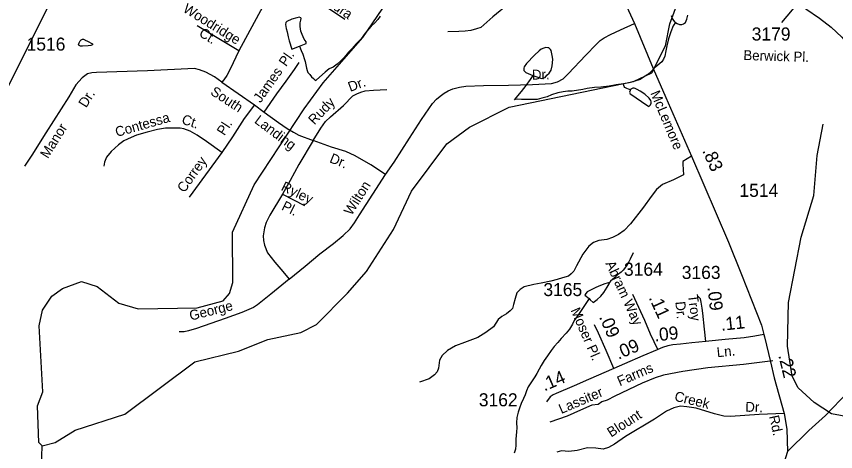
# Model space of a CAD drawing. Extents: x 2082433 to 2279600, y 546599 to 755198.
# Drawn here: x 2132963 to 2140814, y 656269 to 660438 of the extents above; entities that cross this region are included whole.
import ezdxf

# ---------------------------------------------------------------- set-up
doc = ezdxf.new("R2010")
doc.units = 0
for name, color, linetype in [('Exist Hydrographic Misc Water Feature', 7, 'Continuous'), ('Exist Road Non-System Type 51', 7, 'Continuous'), ('Exist Road Non-System Type 51 Label', 7, 'Continuous'), ('Exist Road Secondary Mileage Hundredths English Label', 7, 'Continuous'), ('Exist Road Secondary Type 51 Attributed', 7, 'Continuous'), ('Exist Road Secondary Type 51 Label', 7, 'Continuous'), ('Exist Road Secondary Type 51 Number Label', 7, 'Continuous')]:
    doc.layers.add(name, color=color, linetype=linetype)

msp = doc.modelspace()

# ---------------------------------------------------------------- linework, layer by layer
at = {"layer": 'Exist Hydrographic Misc Water Feature'}
for points in [[(2132697.5, 659397), (2133267.3, 660530.3), (2133583.5, 660799.5), (2134064.4, 661376.8), (2134486.4, 661985), (2134626.5, 662254.4), (2134800.5, 662513.3), (2134915.6, 662904.6), (2135081.5, 663114.4), (2135471.5, 663273.8), (2135853.5, 663531.7), (2136309.6, 664126.1), (2136483.7, 664253.7), (2136708.6, 664327.9), (2137216.5, 664379.9), (2137366.6, 664449)], [(2133211.3, 656322.7), (2133177.2, 656356.2), (2133167.2, 656707.4), (2133217.2, 656840.9), (2133181.4, 657474.7), (2133213.4, 657625), (2133304.4, 657757.7), (2133404.3, 657831), (2133587.4, 657899.5), (2133737.3, 657850.6), (2133946.4, 657692.1), (2134130.3, 657635.9), (2134696.3, 657647.3), (2134946.3, 657714.4), (2135004.3, 657782.1), (2135037.3, 657889.7), (2135034.4, 658371.9), (2135241.3, 658823.7), (2135721.4, 659552.1), (2135903.5, 659800.9), (2136284.5, 660236.1), (2136748.5, 660922.1)], [(2133211.3, 656322.7), (2133336.4, 656356.2), (2133527.3, 656473.7), (2134001.4, 656628.1), (2134673.3, 657129.5), (2135090.4, 657232.5), (2135372.3, 657341.6), (2135689.4, 657410.6), (2135838.4, 657486.3), (2136137.4, 657785.3), (2136319.3, 657994.9), (2136576.4, 658396.3), (2136749.3, 658763.5), (2137089.5, 659215.9), (2137304.4, 659375.5), (2137687.4, 659567.8), (2138877.4, 659815.9), (2139052.5, 659897.6), (2139184.5, 660157.4), (2139225.6, 660366.4), (2139307.6, 660591.1)], [(2135677.5, 660153.1), (2135740.9, 660179.6), (2135739.5, 660193.6), (2135721.2, 660221.5), (2135700.9, 660263.6), (2135688.8, 660297.4), (2135682.9, 660341.3), (2135682.4, 660377.1), (2135688.6, 660403.3), (2135692.1, 660417.3), (2135688.4, 660425.2), (2135672, 660429.3), (2135652.1, 660425), (2135602.1, 660412.7), (2135554.3, 660388.7), (2135546.7, 660378.5), (2135542.4, 660360.5), (2135549, 660322.7), (2135556.8, 660288.6), (2135567.4, 660242.8), (2135579.1, 660202.9), (2135601.7, 660124.8), (2135677.5, 660153.1)], [(2136450, 660440.6), (2136428.2, 660408.6), (2136398.1, 660376.3), (2136364.2, 660344.1), (2136342.5, 660320.2), (2136306.6, 660276.2), (2136266.8, 660223.8), (2136220.9, 660175.5), (2136179.7, 660131.5), (2136147.7, 660095.4), (2136103.6, 660043.2), (2136071.8, 660013.1), (2136038, 659980.9), (2136000.3, 659950.5), (2135961.9, 659934.4), (2135922.6, 659904.4), (2135838.5, 659831.9), (2135832.5, 659824.2)], [(2139237.2, 660446.9), (2139247.5, 660418.9), (2139259.4, 660398.9), (2139273.3, 660383), (2139279.5, 660378.8)], [(2139279.5, 660378.8), (2139295.7, 660369.1), (2139317.2, 660361), (2139339.8, 660361.2), (2139357.4, 660365.4), (2139375, 660379.4), (2139387.1, 660411.2), (2139399, 660449.5)], [(2139279.5, 660378.8), (2139257.5, 660346.9), (2139233.7, 660290.8), (2139213.9, 660222.4), (2139198.3, 660154.7), (2139190.3, 660122.6), (2139188.6, 660106.6), (2139176.7, 660058.6), (2139164.8, 660028.7), (2139148.6, 660002.4), (2139110.9, 659970.3), (2139075.2, 659942.1), (2139047.4, 659910.2), (2139013.5, 659882.1), (2138973.7, 659855.7), (2138939.9, 659833.6), (2138880, 659813.4), (2138833.7, 659801.4), (2138780.2, 659792.9)], [(2133643.8, 660200.4), (2133692.2, 660176.5), (2133693.9, 660170.6), (2133692, 660164.7), (2133676, 660158.6), (2133651.8, 660156.2), (2133597.9, 660154.2), (2133578.4, 660154), (2133565.9, 660157.9), (2133560, 660166.1), (2133563.6, 660186.1), (2133573.9, 660204.1), (2133585.4, 660214.1), (2133595.8, 660220.2), (2133605.5, 660220), (2133617.8, 660214.1), (2133623.9, 660210.3), (2133643.8, 660200.4)], [(2135677.5, 660153.1), (2135693.9, 660111.3), (2135707.7, 660077.2), (2135725.9, 660025.7), (2135731.9, 660007.4), (2135738.4, 659975.6), (2135744.2, 659941.5), (2135748.7, 659919.7), (2135756.3, 659901.5), (2135774.5, 659881.7), (2135792.6, 659859.9), (2135810.4, 659841.8), (2135822.5, 659829.8), (2135832.5, 659824.2)], [(2137914.2, 659871.1), (2137970, 659851.4), (2137994.2, 659843.6), (2138009.8, 659845.7), (2138031.9, 659853.7), (2138048.1, 659873.6), (2138067.6, 659893.7), (2138087.9, 659923.9), (2138097.6, 659963.9), (2138101.2, 659994.1), (2138103.5, 660029.9), (2138098.8, 660063.8), (2138086.9, 660109.8), (2138080.5, 660119.7), (2138066.6, 660135.6), (2138056.7, 660137.5), (2138038.7, 660139.4), (2138018.6, 660133.6), (2137993.2, 660123.2), (2137974.7, 660107.4), (2137929.4, 660067.2), (2137851.5, 659986.9), (2137830, 659954.9), (2137825.4, 659940.9), (2137825.7, 659928.8), (2137827.7, 659918.7), (2137835.9, 659908.9), (2137846, 659900.9), (2137914.2, 659871.1)], [(2137914.2, 659871.1), (2137888.2, 659832.8), (2137844.5, 659775), (2137800.8, 659718.7), (2137748.8, 659656.4), (2137735, 659640.3)], [(2138780.2, 659792.9), (2138712.1, 659782.9), (2138644.2, 659770.4), (2138564.3, 659759.8), (2138502.3, 659755.8), (2138434.7, 659747.4), (2138392.6, 659737.1), (2138290.7, 659722.9), (2138248.7, 659720.7), (2138202.5, 659716.4), (2138150.7, 659704.3), (2138092.4, 659686), (2138050.8, 659667.9), (2137998.9, 659655.5), (2137954.8, 659643.5), (2137914.9, 659641), (2137883.1, 659641), (2137849, 659640.9), (2137805.1, 659642.7), (2137768.9, 659644.5), (2137744.7, 659642.5), (2137735, 659640.3)], [(2138848.2, 659733), (2138830.2, 659741.1), (2138812, 659747.1), (2138794.1, 659757.1), (2138788.2, 659764.9), (2138782, 659788.9), (2138780.2, 659792.9)], [(2138848.2, 659733), (2138843.9, 659727.2), (2138840.3, 659713.2), (2138840.7, 659707), (2138842.5, 659701), (2138850.7, 659693.4), (2138952.6, 659621.6), (2139023, 659574), (2139038.7, 659592.3), (2139046.7, 659608.1), (2139046.7, 659618.3), (2139044.9, 659631.9), (2139028.5, 659655.9), (2138984.6, 659693.8), (2138939.9, 659721.7), (2138912.4, 659737.5), (2138894, 659747.2), (2138882.5, 659751.4), (2138870, 659751.3), (2138852.3, 659741.4), (2138848.2, 659733)], [(2143756.3, 656679), (2143539.4, 656644.1), (2143190.4, 656510.1), (2142933.5, 656357.9), (2142758.3, 656374.6), (2142599.4, 656450), (2142399.3, 656480.3), (2142098.3, 656647.1), (2141740.5, 656585.5), (2141590.4, 656634.5), (2141032.4, 656583.5), (2140774.5, 656631.4), (2140607.3, 656739.8), (2140456.4, 656880.6), (2140397.4, 656990.1), (2140354.3, 657279.7), (2140361.3, 657696.1), (2140483.3, 658323.4), (2140606.4, 658721.2), (2140638.3, 659104.3), (2140695.4, 659404.9)], [(2138875.1, 658174), (2138845.4, 658113.6), (2138831.4, 658085.7), (2138813.8, 658053.5), (2138791.9, 658021.5), (2138779.8, 658005.5), (2138759.9, 657987.4), (2138724, 657961.2), (2138698.4, 657937.1), (2138676.2, 657919), (2138658.4, 657901), (2138650.2, 657892.9), (2138646.5, 657889)], [(2138646.5, 657889), (2138602.4, 657876.6), (2138544.4, 657852.5), (2138510.7, 657836.5), (2138498.6, 657830.3), (2138432.8, 657798), (2138419.1, 657783.9), (2138410.9, 657768.1), (2138453.3, 657734.1)], [(2138453.3, 657734.1), (2138463, 657724.1), (2138491.3, 657696.3), (2138529, 657724.7), (2138564.9, 657758.6), (2138593.2, 657792.8), (2138626.4, 657845), (2138644.6, 657875.1), (2138646.3, 657885), (2138646.5, 657889)], [(2138453.3, 657734.1), (2138419.7, 657688.1), (2138369.5, 657611.7), (2138334, 657561.5), (2138310.2, 657525.8), (2138292.1, 657489.6), (2138264.5, 657443.4), (2138230.6, 657403.1), (2138185.1, 657351.3), (2138150.9, 657315), (2138117.4, 657276.7), (2138089.4, 657236.7), (2138053.9, 657186.5), (2138022.1, 657140.7), (2137991.7, 657094.5), (2137972.1, 657058.2), (2137952.4, 657018.2), (2137930.4, 656984.2), (2137898.7, 656935.9), (2137868.9, 656888), (2137853.1, 656851.9), (2137839.2, 656813.9), (2137823.4, 656777.7), (2137801.7, 656729.5), (2137783.8, 656683.5), (2137771.9, 656647.6), (2137760.2, 656595.4), (2137756.1, 656545.3), (2137758.4, 656497.5), (2137757, 656457.6), (2137751, 656389.6), (2137749.6, 656329.7), (2137745.7, 656293.4), (2137734, 656253.5)], [(2133040.2, 655430.7), (2133114.3, 655475.1), (2133189.3, 655608), (2133211.3, 656322.7)]]:
    msp.add_lwpolyline(points, dxfattribs=at)
at = {"layer": 'Exist Road Non-System Type 51'}
for p, q in [((2134932.1, 659809.5), (2135243.8, 659589.8)), ((2135243.8, 659589.8), (2135337.3, 659521.8)), ((2134933.5, 659135), (2134619, 658705.7)), ((2135513, 658735.5), (2135725.6, 658625))]:
    msp.add_line(p, q, dxfattribs=at)
for points in [[(2137896, 660981.3), (2137907.4, 660913.1), (2137908.4, 660850), (2137896, 660796.2), (2137862.9, 660734.2), (2137814.3, 660671.1), (2137686.1, 660560.5), (2137530, 660434.4), (2137415.3, 660333.1), (2137373.9, 660318.6), (2137317, 660302.1), (2137265.3, 660295.9), (2137203.3, 660293.8), (2137097.9, 660290.7)], [(2135532.9, 660794.2), (2135596.6, 660746), (2135705.7, 660672.3), (2135838.9, 660594.4), (2136112.4, 660411.6)], [(2135095.1, 660107), (2134696.9, 660346.5)], [(2136502, 658922.5), (2136582.8, 659041.5), (2136730.1, 659271), (2136846.3, 659451), (2136952.6, 659604), (2136990.8, 659646.5), (2137023.4, 659674.9), (2137064.5, 659703.2), (2137101.4, 659725.9), (2137146.7, 659744.3), (2137209, 659759.9), (2137271.4, 659769.8), (2137441.4, 659775.5), (2137678, 659779.7), (2137910.4, 659786.8), (2138091.8, 659796.7), (2138149.9, 659810.9), (2138202.3, 659839.2), (2138251.9, 659887.4), (2138421.9, 660067.3), (2138519.7, 660167.9), (2138559.3, 660206.2), (2138596.2, 660233.1), (2138655.7, 660265.7), (2138753.4, 660308.2), (2138887.5, 660370.3)], [(2135337.3, 659521.8), (2135460.6, 659694.7), (2135548.5, 659818), (2135627.8, 659928.5), (2135673.1, 659996.5)], [(2135806.3, 659248.4), (2135881.4, 659368.8), (2135925.4, 659429.7), (2135972.1, 659476.5), (2136096.8, 659585.6), (2136187.5, 659677.7), (2136227.1, 659697.5), (2136264, 659713.1), (2136306.5, 659724.5), (2136385.8, 659731.5), (2136513.4, 659738.6)], [(2133465.1, 659668.5), (2133244.9, 659324.1), (2133110, 659107.6), (2133042.6, 659004.6)], [(2135243.8, 659589.8), (2135147.5, 659459.5), (2135035.6, 659285.2), (2134933.5, 659135)], [(2135337.3, 659521.8), (2135476.2, 659422.7), (2135559.8, 659363.1), (2135617.9, 659329.1), (2135668.9, 659300.8), (2135806.3, 659248.4)], [(2134933.5, 659135), (2134784.8, 659238.5), (2134695.5, 659300.8), (2134630.3, 659337.6), (2134568, 659360.3), (2134534, 659367.4), (2134480.1, 659368.8), (2134390.9, 659367.4), (2134317.2, 659353.2), (2134218, 659327.7), (2134113.2, 659300.8), (2134063.6, 659278.1), (2133994.1, 659245.5), (2133941.7, 659207.3), (2133870.9, 659143.5), (2133827, 659088.3), (2133807.1, 659040.1), (2133800, 659001.8)], [(2135806.3, 659248.4), (2135671.7, 659020.3), (2135588.1, 658867.2), (2135513, 658735.5)], [(2136502, 658922.5), (2136358.9, 659014.6), (2136210.1, 659102.4), (2136120.9, 659144.9), (2135983.4, 659184.6), (2135806.3, 659248.4)], [(2139433.3, 659098.7), (2139393, 659073.8), (2139350.6, 659048), (2139350.6, 659023.2), (2139357.5, 658919.4), (2139261.2, 658871.2), (2139156.3, 658828.7), (2139096.8, 658780.6), (2139045.8, 658712.6), (2138972.1, 658610.5), (2138847.4, 658451.8), (2138787.9, 658386.7), (2138734.1, 658349.8), (2138677.4, 658318.7), (2138620.7, 658301.7), (2138544.2, 658290.3), (2138518.7, 658281.8), (2138493.2, 658270.5), (2138447.9, 658236.5), (2138391.2, 658160), (2138331.7, 658049.5), (2138306.2, 657998.4), (2138280.7, 657972.9), (2138255.2, 657950.3), (2138195.7, 657933.3), (2138144.7, 657919.1), (2138085.2, 657902.1), (2137991.6, 657882.3), (2137923.6, 657870.9), (2137830.1, 657848.3), (2137790.5, 657822.8), (2137759.3, 657788.7), (2137742.3, 657734.9), (2137728.1, 657678.2), (2137716.8, 657638.6), (2137696.9, 657615.9), (2137660.1, 657587.5), (2137614.8, 657562), (2137580.8, 657533.7), (2137535.4, 657465.7), (2137461.7, 657409), (2137385.2, 657360.8), (2137257.7, 657312.7), (2137172.7, 657281.5), (2137093.3, 657236.2), (2137045.2, 657190.8), (2137016.8, 657145.5), (2137008.3, 657069), (2136997, 657032.1), (2136971.5, 657003.8), (2136917.7, 656967), (2136827, 656933)], [(2135576.8, 657920.8), (2135731.2, 658046.9), (2135871.5, 658164.5), (2136001.9, 658262.2), (2136095.4, 658338.7), (2136160.6, 658402.5), (2136204.5, 658462), (2136251.2, 658537.1), (2136380.2, 658735.5), (2136502, 658922.5)], [(2135513, 658735.5), (2135392.6, 658534.3), (2135358.6, 658463.4), (2135341.6, 658411), (2135327.4, 658337.3), (2135331.7, 658292), (2135341.6, 658245.2), (2135371.4, 658173), (2135440.8, 658083.7), (2135515.9, 657993), (2135576.8, 657920.8)], [(2135576.8, 657920.8), (2135401.1, 657776.2), (2135273.6, 657674.2), (2135236.7, 657650.1), (2135123.4, 657600.5), (2134963.3, 657543.9), (2134688.4, 657447.5), (2134613.3, 657426.3), (2134572.2, 657417.8), (2134522.6, 657416.4)], [(2140213.3, 657139.8), (2139932.8, 657103), (2139589.9, 657071.8), (2139349, 657037.8), (2139164.8, 657001), (2139085.5, 656975.5), (2138960.8, 656924.4), (2138697.3, 656799.8), (2138623.6, 656762.9), (2138575.4, 656745.9), (2138538.6, 656720.4), (2138479.1, 656714.8), (2138368.5, 656666.6), (2138241, 656609.9), (2138076.7, 656550.4)], [(2140321, 656635.4), (2140080.1, 656624.1), (2139808.1, 656604.2), (2139742.9, 656609.9), (2139655.1, 656629.7), (2139476.5, 656683.6), (2139388.7, 656697.7), (2139326.4, 656703.4), (2139264, 656689.2), (2139193.2, 656655.2), (2139077, 656578.7), (2138802.1, 656414.4), (2138694.4, 656340.7), (2138637.7, 656306.7), (2138586.7, 656292.5), (2138515.9, 656301), (2138436.5, 656303.9), (2138337.4, 656278.4), (2138258, 656269.9), (2138187.2, 656275.5), (2138141.8, 656264.2)]]:
    msp.add_lwpolyline(points, dxfattribs=at)
at = {"layer": 'Exist Road Secondary Type 51 Attributed'}
for points in [[(2136295.2, 661983), (2135963.6, 661450.2), (2135837.5, 661249), (2135685.9, 661003.9), (2135532.9, 660794.2), (2135428, 660669.5), (2135377, 660601.5), (2135324.6, 660532.1), (2135095.1, 660107), (2135012.9, 659934.1), (2134978.9, 659871.8), (2134950.5, 659829.3), (2134932.1, 659809.5), (2134861.3, 659859.1), (2134777.7, 659903), (2134719.6, 659927.1), (2134670, 659938.4), (2134220.5, 659917.1), (2133732.7, 659901.6), (2133687.2, 659897.7), (2133644.5, 659888.7), (2133592.9, 659849.6), (2133532.5, 659782.1), (2133465.1, 659668.5)], [(2138437.7, 661447.6), (2138527.7, 661200.5), (2138605.2, 660993.7), (2138717.9, 660740.4), (2138887.5, 660370.3), (2139064.3, 659940.2), (2139187.3, 659662.1), (2139433.3, 659098.7), (2139786.9, 658274.7), (2139912, 657964.5), (2140102.8, 657479.6), (2140125.7, 657391.8)], [(2140068.3, 661326.9), (2140067.1, 661289.4), (2140070.2, 661253.2), (2140103.3, 661187), (2140273.8, 660906.1), (2140350, 660712.3), (2140444.1, 660595.7), (2140529.3, 660511.9), (2140659.3, 660420.7), (2140772.8, 660335.5), (2140873.7, 660239.8), (2140936.4, 660166.6), (2141014.1, 660045.4), (2141100.8, 659875), (2141366, 659341.2), (2141771.7, 658523.3), (2141988.2, 658140.4), (2142061.9, 657993), (2142131.3, 657834.3)], [(2142131.3, 657834.3), (2141927.3, 657711.1), (2141568.6, 657512.5), (2141405.6, 657393.4), (2141340.4, 657331.1), (2141218.6, 657185.2), (2140932.4, 656839.4), (2140717, 656615.6), (2140558.3, 656471), (2140354.3, 656269.9)], [(2139110.1, 657246), (2139041.4, 657392.6), (2138985.4, 657525.8), (2138871.7, 657774.1)], [(2139569.4, 657323.3), (2139558, 657442.9), (2139540.8, 657596.1), (2139534.3, 657642.8), (2139527.1, 657700.4), (2139520.7, 657732), (2139487.6, 657763.7)], [(2138689.9, 657064.7), (2138614.5, 657238.2), (2138543.2, 657403.1), (2138503.6, 657484.7)], [(2140125.7, 657391.8), (2140040.8, 657374.3), (2139939.1, 657358.9), (2139756.2, 657343.4), (2139598.2, 657326.3), (2139569.4, 657323.3)], [(2140125.7, 657391.8), (2140132.2, 657366.8), (2140189.1, 657128.9), (2140226.3, 656976.2), (2140321, 656635.4), (2140346.5, 656482.4), (2140354.3, 656269.9)], [(2139569.4, 657323.3), (2139434.9, 657309.4), (2139328, 657298.5), (2139255, 657290.8), (2139206.5, 657281), (2139156.4, 657265.5), (2139110.1, 657246)], [(2139110.1, 657246), (2139103.8, 657243.3), (2138967.6, 657185), (2138791.4, 657108.7), (2138689.9, 657064.7)], [(2138689.9, 657064.7), (2138687.7, 657063.7), (2138447.3, 656959.6), (2138308.1, 656899.3), (2138137, 656825.6), (2138106, 656814.2), (2138078.1, 656792.6), (2138045.1, 656744.5)], [(2140354.3, 656269.9), (2140303.3, 656106.9), (2140233.9, 655941.1)]]:
    msp.add_lwpolyline(points, dxfattribs=at)
at = {"layer": 'Exist Road Secondary Type 51 Number Label'}
msp.add_lwpolyline([(2141085.3, 661698.9), (2140854.4, 661047.8), (2140295.6, 660378.2)], dxfattribs=at)

# ---------------------------------------------------------------- texts
at = {"layer": 'Exist Road Non-System Type 51 Label'}
for s, rotation, p in [('Sandra', 325.82119, (2135805.1, 660636.9)), ('Woodridge', 328.09084, (2134552.3, 660487.7)), ('Ct.', 328.09084, (2134705.5, 660255)), ('Pl.', 54.84467, (2135547.9, 659950.9)), ('James', 54.84467, (2135303.1, 659603.3)), ('Dr.', 1.60365, (2137905.1, 659831.5)), ('Dr.', 20.23818, (2136162.4, 659714.2)), ('Dr.', 57.88763, (2133631.9, 659556.5)), ('South', 327.01186, (2134815.8, 659694.7)), ('Rudy', 46.29334, (2135818.7, 659393.5)), ('Contessa', 15.95601, (2133925.9, 659282.3)), ('Ct.', 341.5528, (2134540, 659412.7)), ('Landing', 323.11003, (2135236.8, 659424.1)), ('Manor', 57.88763, (2133265.1, 659070)), ('Pl.', 56.81218, (2134956.3, 659289.3)), ('Correy', 54.48172, (2134573.4, 658742.5)), ('Dr.', 337.73673, (2135957.3, 659043)), ('Ryley', 333.88839, (2135492.4, 658776.6)), ('Wilton', 57.63783, (2136174.8, 658524.5)), ('Pl.', 333.88839, (2135497.5, 658589.6)), ('George', 14.04591, (2134634.3, 657523.3)), ('Creek', 346.42037, (2139263.6, 656757.2)), ('Dr.', 358.08947, (2139947.3, 656651.1)), ('Blount', 32.65616, (2138662.8, 656402.9))]:
    msp.add_text(s, height=95, rotation=rotation, dxfattribs=at).set_placement(p)
at = {"layer": 'Exist Road Secondary Mileage Hundredths English Label'}
for s, rotation, p in [('.83', 293.57609, (2139533.9, 659152.3)), ('.09', 276.42568, (2139586.3, 657843.4)), ('.11', 294.60011, (2139021.3, 657743.6)), ('.09', 293.38787, (2138545, 657559)), ('.11', 6.15815, (2139719.4, 657425.9)), ('.09', 5.79574, (2139081.7, 657323.6)), ('.09', 23.42746, (2138732.9, 657147.8)), ('.22', 283.70584, (2140264.5, 657189.2)), ('.14', 23.43469, (2138023.8, 656844.7))]:
    msp.add_text(s, height=125, rotation=rotation, dxfattribs=at).set_placement(p)
at = {"layer": 'Exist Road Secondary Type 51 Label'}
for s, rotation, p in [('Berwick Pl.', 358.36035, (2139929.5, 660020.1)), ('McLemore', 292.82649, (2139036.9, 659703.5)), ('Abram Way', 294.60009, (2138606.9, 658071.3)), ('Troy', 277.1215, (2139399.4, 657767.8)), ('Dr.', 275.42291, (2139278.1, 657703.8)), ('Moser Pl.', 293.38786, (2138272.5, 657623.6)), ('Ln.', 5.79572, (2139679.9, 657172.4)), ('Farms', 23.42744, (2138746, 656894.5)), ('Lassiter', 23.29575, (2138185.6, 656628.2)), ('Rd.', 282.32874, (2140176.4, 656606.6))]:
    msp.add_text(s, height=95, rotation=rotation, dxfattribs=at).set_placement(p)
at = {"layer": 'Exist Road Secondary Type 51 Number Label'}
for s, p in [('3179', (2140010, 660207)), ('1516', (2133061.1, 660110.1)), ('1514', (2139892.6, 658709.2)), ('3164', (2138786.2, 657953.4)), ('3163', (2139339.9, 657922.9)), ('3165', (2138014, 657758.8)), ('3162', (2137395, 656702.7))]:
    msp.add_text(s, height=125, dxfattribs=at).set_placement(p)

doc.saveas('drawing.dxf')
